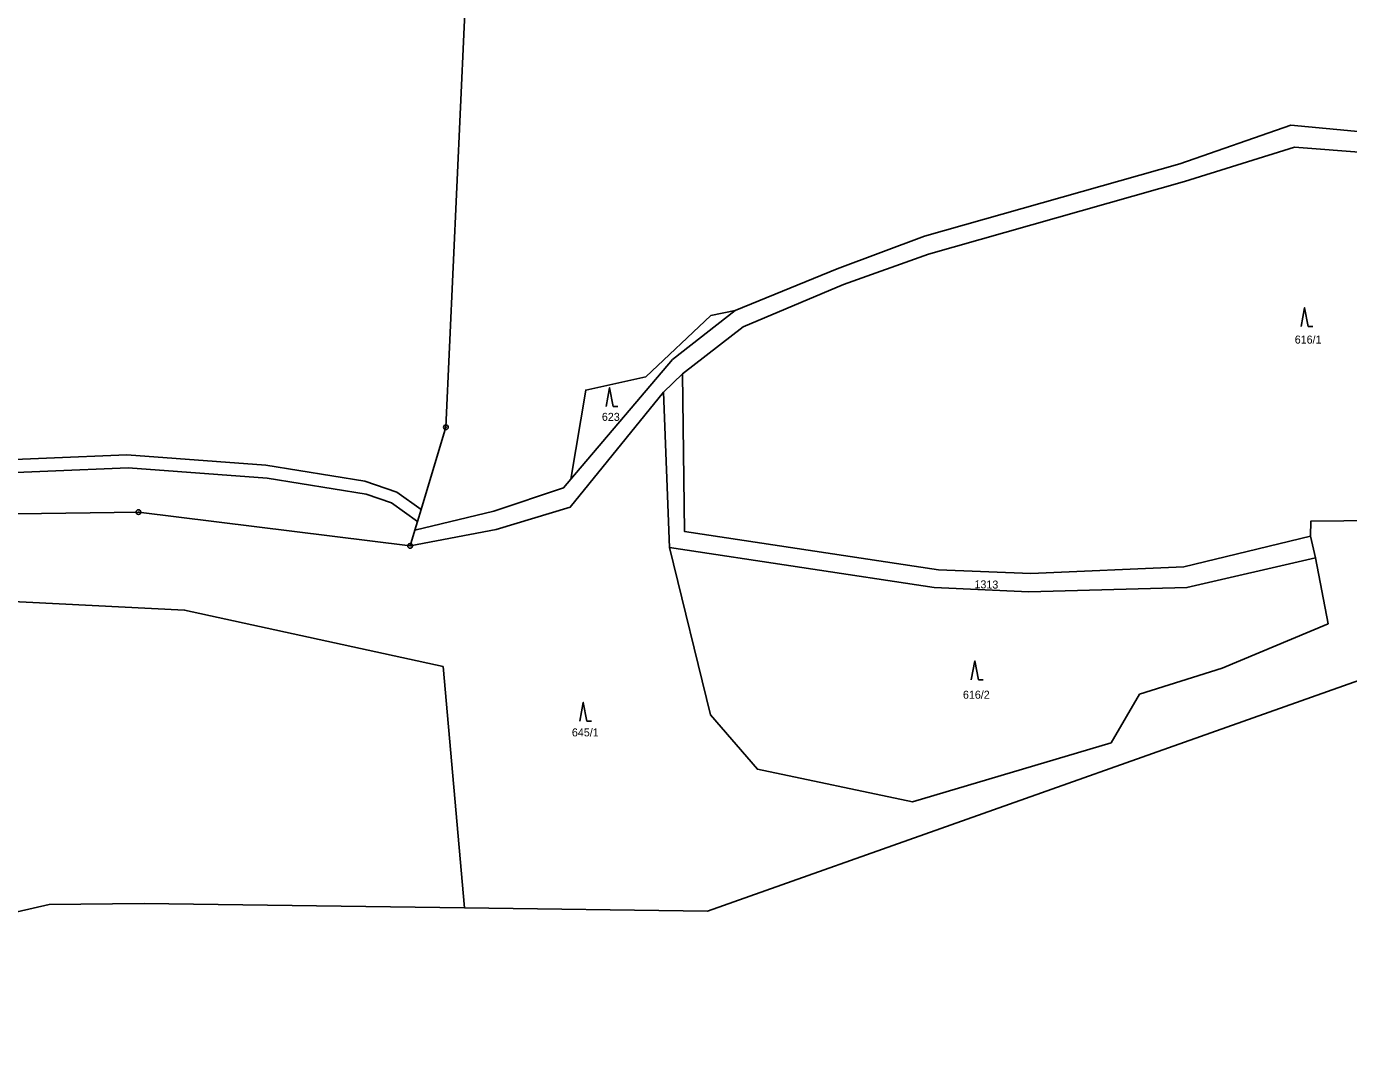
# Model space of a CAD drawing. Extents: x -872229 to -869198, y -1075981 to -1074329.
# Drawn here: x -870040 to -869759.2, y -1075751.2 to -1075531.8 of the extents above; entities that cross this region are included whole.
import ezdxf

# ---------------------------------------------------------------- set-up
doc = ezdxf.new("R2010")
doc.units = 0
doc.header["$LTSCALE"] = 0.68
for name, color, linetype, lineweight in [('1', 7, 'Continuous', 25), ('3', 7, 'Continuous', 25), ('8', 7, 'Continuous', 25)]:
    doc.layers.add(name, color=color, linetype=linetype, lineweight=lineweight)
doc.layers.add('2', color=7, linetype='Continuous')

msp = doc.modelspace()

# ---------------------------------------------------------------- linework, layer by layer
at = {"layer": '1'}
for p, q in [((-870015.01, -1075718.11), (-869946.97, -1075719.04)), ((-869946.97, -1075719.04), (-869895.39, -1075719.74))]:
    msp.add_line(p, q, dxfattribs=at)
for points in [[(-869956.21, -1075634.42), (-869950.93, -1075616.94), (-869945.48, -1075497.93), (-869942.3, -1075409.15)], [(-869889.5, -1075592.13), (-869867.84, -1075583.27), (-869849.28, -1075576.32), (-869795.03, -1075560.97), (-869771.51, -1075552.75), (-869740.67, -1075555.67), (-869710.85, -1075550.74), (-869675.12, -1075544), (-869656.72, -1075536.14)], [(-869657.44, -1075540.59), (-869674.12, -1075547.66), (-869710.28, -1075554.3), (-869740.46, -1075559.8), (-869770.69, -1075557.44), (-869794.04, -1075564.75), (-869848.43, -1075580.14), (-869866.49, -1075586.59), (-869887.81, -1075595.64), (-869900.72, -1075605.56)], [(-870360.91, -1075564.7), (-870334.21, -1075571.6), (-870312.37, -1075586.81), (-870293.77, -1075595.76), (-870270.86, -1075602.02), (-870243.34, -1075610.77), (-870217.09, -1075618.71), (-870179.15, -1075630.08), (-870157.97, -1075632.03), (-870128.13, -1075632.63), (-870114.57, -1075631.72), (-870098.39, -1075625.25), (-870092.04, -1075619.77), (-870087.29, -1075619.63), (-870052.6, -1075626.97), (-870018.4, -1075625.53), (-869988.87, -1075627.77), (-869967.84, -1075631.16), (-869962.49, -1075632.97), (-869956.97, -1075636.94), (-869956.21, -1075634.42)], [(-869956.21, -1075634.42), (-869961.39, -1075630.69), (-869968.14, -1075628.41), (-869989.17, -1075625.02), (-870018.7, -1075622.78), (-870052.9, -1075624.22), (-870087.59, -1075616.88), (-870093.16, -1075617.33), (-870100.3, -1075623.21), (-870115.61, -1075629.33), (-870126.17, -1075630.04), (-870156.01, -1075629.44), (-870177.19, -1075627.49), (-870215.13, -1075616.12), (-870241.38, -1075608.18), (-870268.9, -1075599.43), (-870291.81, -1075593.17), (-870310.41, -1075584.22), (-870332.25, -1075569.01)], [(-870319.49, -1075589.3), (-870295.19, -1075603.73), (-870207.28, -1075631.27), (-870168.61, -1075639.64), (-870121.56, -1075638.1), (-870072.83, -1075635.74), (-870016.23, -1075634.96), (-869958.54, -1075642.14), (-869957.53, -1075638.79), (-869956.97, -1075636.94)], [(-869924.37, -1075627.94), (-869902.8, -1075602.53), (-869889.5, -1075592.13)], [(-869924.37, -1075627.94), (-869921.22, -1075609.04), (-869908.51, -1075606.2), (-869894.67, -1075593.21), (-869889.5, -1075592.13)], [(-869946.97, -1075719.04), (-869951.52, -1075667.78), (-870006.44, -1075655.77), (-870192.84, -1075646.38), (-870362.26, -1075599.45), (-870356.17, -1075620.52)], [(-869767.28, -1075640.08), (-869794.22, -1075646.61), (-869826.72, -1075648), (-869846.35, -1075647.25), (-869900.26, -1075639.11), (-869900.72, -1075605.56), (-869904.69, -1075609.48), (-869903.45, -1075642.46)], [(-869904.69, -1075609.48), (-869924.54, -1075633.93), (-869940.24, -1075638.66), (-869958.54, -1075642.14)], [(-869957.53, -1075638.79), (-869940.75, -1075634.78), (-869925.94, -1075629.8), (-869924.37, -1075627.94)], [(-869895.39, -1075719.74), (-869729.92, -1075661.11), (-869666.68, -1075657.35), (-869593.09, -1075655.24), (-869520.45, -1075655.26), (-869463.49, -1075641.67), (-869392.24, -1075631.04), (-869390.16, -1075631.43)], [(-869767.28, -1075640.08), (-869767.22, -1075636.85), (-869725.35, -1075636.46), (-869675.65, -1075632.94)], [(-869903.45, -1075642.46), (-869847.25, -1075650.97), (-869827.1, -1075651.9), (-869793.57, -1075650.99), (-869766.26, -1075644.69), (-869767.28, -1075640.08)], [(-869903.45, -1075642.46), (-869894.75, -1075678.04), (-869884.79, -1075689.57), (-869851.82, -1075696.48), (-869809.65, -1075683.99), (-869803.62, -1075673.66), (-869786.07, -1075668.09), (-869763.58, -1075658.67), (-869766.26, -1075644.69)], [(-870179.01, -1075751.24), (-870035.17, -1075718.28), (-870015.01, -1075718.11)]]:
    msp.add_lwpolyline(points, dxfattribs=at)
at = {"layer": '3'}
for p, q in [((-869767.82, -1075595.55), (-869766.824, -1075595.55)), ((-869915.41, -1075612.55), (-869914.414, -1075612.55)), ((-869837.85, -1075670.58), (-869836.854, -1075670.58)), ((-869921.01, -1075679.37), (-869920.014, -1075679.37))]:
    msp.add_line(p, q, dxfattribs=at)
for points in [[(-869767.82, -1075595.55), (-869768.57, -1075591.55), (-869769.32, -1075595.55)], [(-869915.41, -1075612.55), (-869916.16, -1075608.55), (-869916.91, -1075612.55)], [(-869837.85, -1075670.58), (-869838.6, -1075666.58), (-869839.35, -1075670.58)], [(-869921.01, -1075679.37), (-869921.76, -1075675.37), (-869922.51, -1075679.37)]]:
    msp.add_lwpolyline(points, dxfattribs=at)
at = {"layer": '8'}
for centre, radius in [((-869950.93, -1075616.9399), 0.5), ((-869950.93, -1075616.9399), 0.0303), ((-870016.23, -1075634.9599), 0.5), ((-870016.23, -1075634.9599), 0.0303), ((-869958.54, -1075642.1399), 0.5), ((-869958.54, -1075642.1399), 0.0303)]:
    msp.add_circle(centre, radius, dxfattribs=at)

# ---------------------------------------------------------------- texts
at = {"layer": '2'}
for s, p in [('616/1', (-869770.66, -1075599.17)), ('623', (-869917.81, -1075615.58)), ('616/2', (-869841.13, -1075674.6)), ('645/1', (-869924.18, -1075682.6))]:
    msp.add_text(s, height=1.7, dxfattribs=at).set_placement(p)
msp.add_text('1313', height=1.7, rotation=359, dxfattribs=at).set_placement((-869838.694, -1075651.129))

doc.saveas('drawing.dxf')
